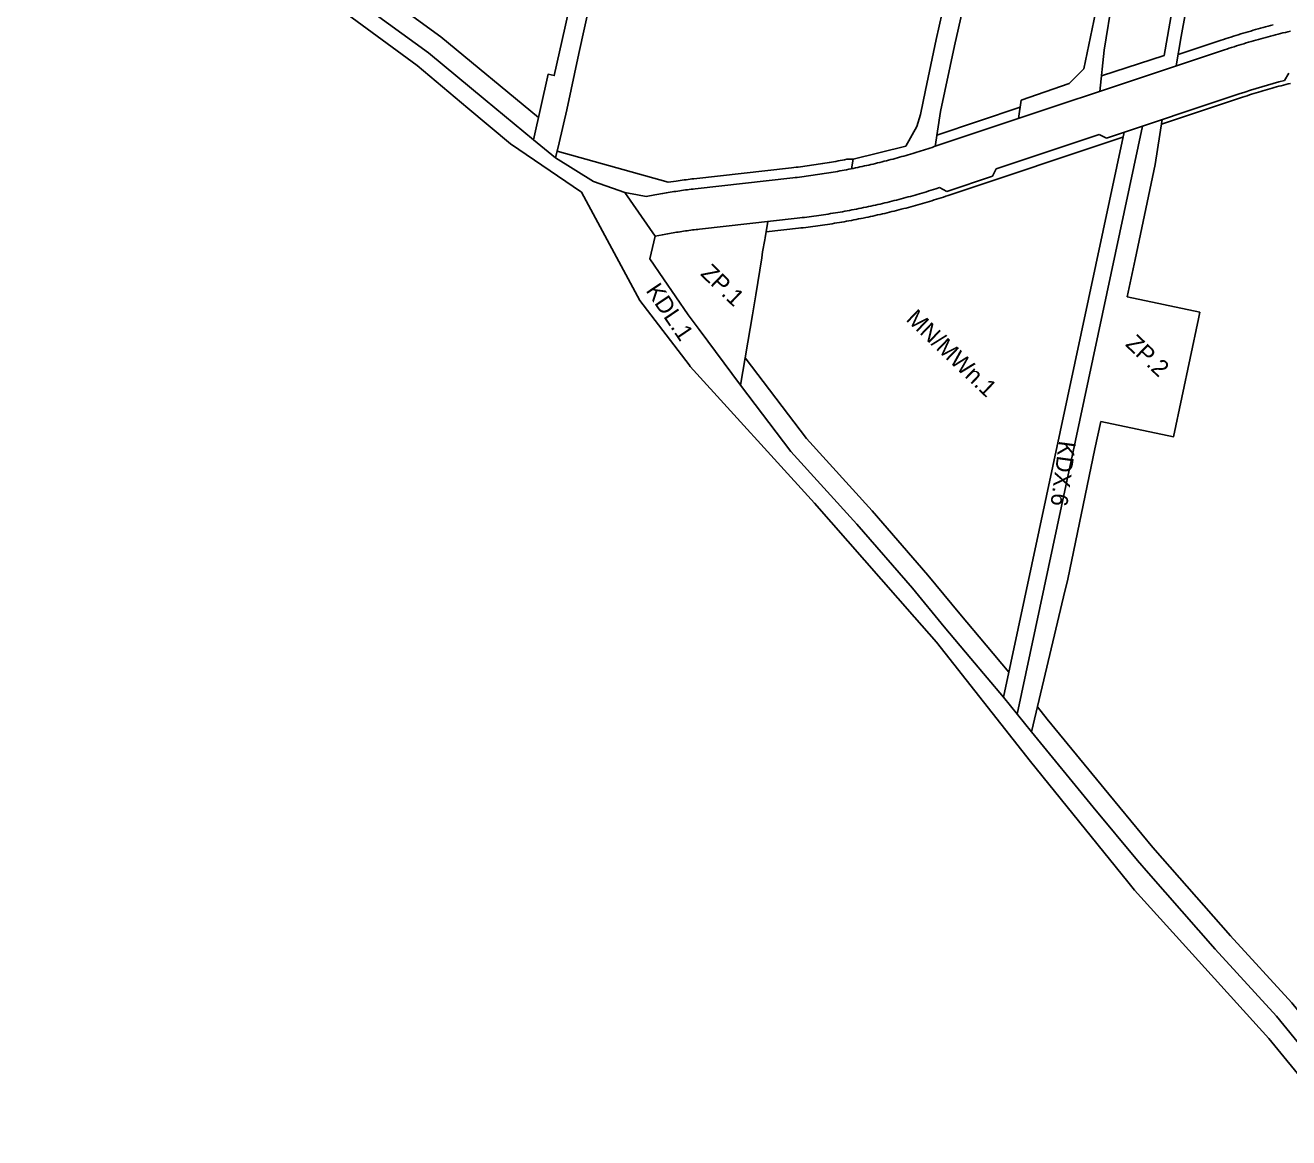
# Model space of a CAD drawing. Extents: x 7420063 to 7422255, y 5550978 to 5552824.
# Drawn here: x 7420947.8 to 7421321.6, y 5551350.9 to 5551680 of the extents above; entities that cross this region are included whole.
import ezdxf

# ---------------------------------------------------------------- set-up
doc = ezdxf.new("R2010")
doc.units = 0
for name, color, linetype in [('linie_rozgraniczajace', 7, 'Continuous'), ('linie_zabudowy_nieprzekraczalne', 7, 'Continuous'), ('oznaczenia_przeznaczen', 7, 'Continuous')]:
    doc.layers.add(name, color=color, linetype=linetype)

msp = doc.modelspace()

# ---------------------------------------------------------------- linework, layer by layer
at = {"layer": 'linie_rozgraniczajace'}
for p, q in [((7421320.41, 5551663.66), (7421321.64, 5551665.78)), ((7421306.95, 5551659.68), (7421267.73, 5551646.59)), ((7421241.3, 5551476.18), (7421278.41, 5551650.15)), ((7421265.52, 5551647.69), (7421267.73, 5551646.59)), ((7421233.99, 5551635.32), (7421235.1, 5551637.54)), ((7421220.51, 5551630.82), (7421218.28, 5551631.94)), ((7421233.99, 5551635.32), (7421220.51, 5551630.82)), ((7421134.22, 5551617.6), (7421125.18, 5551630.5)), ((7421295.35, 5551595.07), (7421273.84, 5551599.61))]:
    msp.add_line(p, q, dxfattribs=at)
for points in [[(7421098.19, 5551646.12), (7421102.49, 5551665.51), (7421104.31, 5551665.11), (7421107.41, 5551679.09), (7421110.27, 5551692), (7421113.2, 5551705.2), (7421116.05, 5551718.08), (7421118.99, 5551731.32), (7421121.85, 5551744.22), (7421124.78, 5551757.44), (7421127.64, 5551770.35), (7421130.57, 5551783.55), (7421133.44, 5551796.48), (7421136.37, 5551809.71), (7421139.22, 5551822.56), (7421142.14, 5551835.73), (7421147.18, 5551858.45), (7421142.87, 5551860.3), (7421144.36, 5551866.42)], [(7421154.11, 5551861.98), (7421150.54, 5551847.7), (7421144.27, 5551819.9), (7421143.15, 5551814.43), (7421141.13, 5551804.53), (7421134.5, 5551774.39), (7421133.74, 5551771.02), (7421126.58, 5551739.63), (7421111.64, 5551671.6), (7421108.05, 5551654.98), (7421105.74, 5551645.24), (7421104.68, 5551640.75)], [(7421192.24, 5551637.54), (7421192.8, 5551640.35), (7421208.3, 5551644.25), (7421211.64, 5551650.08), (7421212.65, 5551653.59), (7421214.19, 5551660.83), (7421217.37, 5551675.81), (7421220.84, 5551691.66), (7421224.12, 5551706.65), (7421227.62, 5551722.48), (7421230.93, 5551737.47), (7421234.37, 5551753.31), (7421237.62, 5551768.3), (7421241.08, 5551784.04), (7421244.4, 5551799.11), (7421248.11, 5551814.8), (7421251.22, 5551827.95)], [(7421256.32, 5551825.11), (7421251.4, 5551804.81), (7421243.81, 5551770.35), (7421239.56, 5551750.39), (7421236.22, 5551735.65), (7421232.72, 5551720.18), (7421226.82, 5551691.85), (7421222.72, 5551673.94), (7421218.61, 5551654.49), (7421217.04, 5551644.16)], [(7421241.69, 5551652.39), (7421242.49, 5551657.78), (7421256.68, 5551662.77), (7421261.06, 5551667.1), (7421264.93, 5551686), (7421270.26, 5551710.97), (7421275.92, 5551735.91), (7421281.27, 5551760.62), (7421286.7, 5551785.33), (7421291.46, 5551806.11)], [(7421295.18, 5551804.27), (7421289.3, 5551778.54), (7421287.92, 5551772.52), (7421285.32, 5551760.42), (7421281.44, 5551742.32), (7421280.86, 5551739.61), (7421277.39, 5551724.32), (7421276.81, 5551721.74), (7421273.3, 5551706.31), (7421272.66, 5551703.48), (7421269.89, 5551690.5), (7421269.46, 5551687.86), (7421266.99, 5551672.6), (7421265.78, 5551660.43)], [(7421266.23, 5551664.98), (7421284.76, 5551671.04), (7421287.2, 5551684.55), (7421290.87, 5551702.58), (7421294.72, 5551720.59), (7421298.61, 5551738.59), (7421302.65, 5551756.59), (7421306.63, 5551774.62), (7421310.59, 5551773.73), (7421303.16, 5551740.66), (7421301.45, 5551732.77), (7421298.14, 5551717.54), (7421292.21, 5551689.64), (7421289.79, 5551676.65), (7421288.34, 5551667.96)], [(7420943.09, 5551758.24), (7420950.48, 5551752.68), (7420965.32, 5551741.49), (7420966.91, 5551740.29), (7420981.78, 5551730.96), (7420990.3, 5551725.62), (7421000.22, 5551719.39), (7421009.04, 5551713.08), (7421019.38, 5551705.78), (7421029.95, 5551698.3), (7421047.42, 5551686.17), (7421067.1, 5551671.85), (7421083.92, 5551657.93), (7421098.19, 5551646.12), (7421104.68, 5551640.75)], [(7421339.77, 5551350.86), (7421315.74, 5551380.18), (7421275.97, 5551424.11), (7421274.02, 5551426.53), (7421245.28, 5551462.15), (7421217.47, 5551497.45), (7421210.95, 5551504.89), (7421181.34, 5551538.61), (7421144.57, 5551579.08), (7421144.2, 5551579.56), (7421129.6, 5551598.59), (7421112.4, 5551630.57), (7421091.37, 5551644.86), (7421078.71, 5551655.49), (7421063.74, 5551668.05), (7421026.78, 5551695.28)], [(7421131.49, 5551629.29), (7421134.09, 5551629.8), (7421134.66, 5551629.9), (7421135.22, 5551630.01), (7421135.78, 5551630.11), (7421136.35, 5551630.21), (7421136.91, 5551630.31), (7421137.48, 5551630.4), (7421138.04, 5551630.5), (7421138.61, 5551630.59), (7421139.17, 5551630.68), (7421139.74, 5551630.77), (7421140.31, 5551630.85), (7421140.87, 5551630.94), (7421141.44, 5551631.02), (7421142.01, 5551631.1), (7421142.58, 5551631.18), (7421143.14, 5551631.25), (7421143.71, 5551631.32), (7421144.28, 5551631.4), (7421144.85, 5551631.46), (7421145.42, 5551631.53), (7421145.98, 5551631.6), (7421174.89, 5551634.84), (7421175.56, 5551634.91), (7421176.23, 5551634.99), (7421176.89, 5551635.07), (7421177.56, 5551635.15), (7421178.22, 5551635.24), (7421178.89, 5551635.33), (7421179.55, 5551635.41), (7421180.22, 5551635.51), (7421180.88, 5551635.6), (7421181.55, 5551635.69), (7421182.21, 5551635.79), (7421182.87, 5551635.89), (7421183.54, 5551635.99), (7421184.2, 5551636.1), (7421184.86, 5551636.21), (7421185.52, 5551636.31), (7421186.19, 5551636.42), (7421186.85, 5551636.54), (7421187.51, 5551636.65), (7421188.17, 5551636.77), (7421188.83, 5551636.89), (7421189.49, 5551637.01), (7421190.15, 5551637.14), (7421190.81, 5551637.26), (7421191.47, 5551637.39), (7421192.13, 5551637.52), (7421192.79, 5551637.65), (7421193.44, 5551637.79), (7421194.1, 5551637.93), (7421194.76, 5551638.06), (7421195.42, 5551638.21), (7421196.07, 5551638.35), (7421196.73, 5551638.49), (7421197.38, 5551638.64), (7421198.04, 5551638.79), (7421198.69, 5551638.94), (7421199.35, 5551639.1), (7421200, 5551639.26), (7421200.65, 5551639.41), (7421201.3, 5551639.57), (7421201.95, 5551639.74), (7421202.61, 5551639.9), (7421203.26, 5551640.07), (7421203.91, 5551640.24), (7421204.56, 5551640.41), (7421205.2, 5551640.58), (7421205.85, 5551640.76), (7421206.5, 5551640.94), (7421207.15, 5551641.12), (7421207.79, 5551641.3), (7421208.44, 5551641.48), (7421209.08, 5551641.67), (7421209.73, 5551641.86), (7421210.37, 5551642.05), (7421211.01, 5551642.24), (7421211.65, 5551642.43), (7421212.29, 5551642.63), (7421212.93, 5551642.83), (7421213.57, 5551643.03), (7421214.21, 5551643.23), (7421214.85, 5551643.44), (7421215.49, 5551643.65), (7421216.12, 5551643.85), (7421216.77, 5551644.07), (7421302.6, 5551672.72), (7421303.31, 5551672.96), (7421304.02, 5551673.19), (7421304.73, 5551673.42), (7421305.45, 5551673.65), (7421306.17, 5551673.88), (7421306.88, 5551674.1), (7421307.6, 5551674.32), (7421308.32, 5551674.54), (7421309.04, 5551674.76), (7421309.76, 5551674.97), (7421310.48, 5551675.19), (7421311.21, 5551675.4), (7421311.93, 5551675.6), (7421312.65, 5551675.81), (7421313.38, 5551676.01), (7421314.1, 5551676.21), (7421314.83, 5551676.41), (7421315.56, 5551676.6), (7421316.28, 5551676.79), (7421317.01, 5551676.98), (7421317.74, 5551677.17), (7421318.47, 5551677.35), (7421319.2, 5551677.53), (7421319.93, 5551677.71), (7421320.67, 5551677.89), (7421321.4, 5551678.06), (7421322.13, 5551678.24)], [(7421284.18, 5551652.08), (7421282.12, 5551638.77), (7421276.2, 5551610.7), (7421273.84, 5551599.61)], [(7421235.1, 5551637.54), (7421265.52, 5551647.69)], [(7421237.26, 5551481.2), (7421272.9, 5551648.31)], [(7421125.18, 5551630.5), (7421115.9, 5551633.76), (7421104.68, 5551640.75)], [(7421134.22, 5551617.6), (7421136.34, 5551618.01), (7421136.86, 5551618.11), (7421137.38, 5551618.2), (7421137.9, 5551618.3), (7421138.43, 5551618.39), (7421138.95, 5551618.48), (7421139.47, 5551618.57), (7421139.99, 5551618.66), (7421140.51, 5551618.74), (7421141.03, 5551618.82), (7421141.56, 5551618.91), (7421142.08, 5551618.99), (7421142.6, 5551619.06), (7421143.13, 5551619.14), (7421143.65, 5551619.21), (7421144.18, 5551619.28), (7421144.7, 5551619.35), (7421145.22, 5551619.42), (7421145.75, 5551619.49), (7421146.27, 5551619.55), (7421146.8, 5551619.61), (7421147.33, 5551619.67), (7421176.24, 5551622.91), (7421176.94, 5551622.99), (7421177.64, 5551623.08), (7421178.35, 5551623.16), (7421179.05, 5551623.25), (7421179.76, 5551623.34), (7421180.46, 5551623.43), (7421181.16, 5551623.52), (7421181.87, 5551623.62), (7421182.57, 5551623.72), (7421183.27, 5551623.82), (7421183.98, 5551623.92), (7421184.68, 5551624.03), (7421185.38, 5551624.14), (7421186.08, 5551624.25), (7421186.78, 5551624.36), (7421187.49, 5551624.48), (7421188.19, 5551624.59), (7421188.89, 5551624.71), (7421189.59, 5551624.83), (7421190.29, 5551624.96), (7421190.99, 5551625.09), (7421191.69, 5551625.21), (7421192.39, 5551625.35), (7421193.08, 5551625.48), (7421193.78, 5551625.62), (7421194.48, 5551625.75), (7421195.18, 5551625.89), (7421195.87, 5551626.04), (7421196.57, 5551626.18), (7421197.27, 5551626.33), (7421197.96, 5551626.48), (7421198.66, 5551626.63), (7421199.35, 5551626.78), (7421200.04, 5551626.94), (7421200.74, 5551627.1), (7421201.43, 5551627.26), (7421202.12, 5551627.42), (7421202.81, 5551627.59), (7421203.5, 5551627.76), (7421204.19, 5551627.93), (7421204.88, 5551628.1), (7421205.57, 5551628.28), (7421206.26, 5551628.45), (7421206.95, 5551628.63), (7421207.64, 5551628.81), (7421208.32, 5551629), (7421209.01, 5551629.18), (7421209.69, 5551629.37), (7421210.38, 5551629.56), (7421211.06, 5551629.75), (7421211.75, 5551629.95), (7421212.43, 5551630.15), (7421213.11, 5551630.34), (7421213.79, 5551630.55), (7421214.47, 5551630.75), (7421215.15, 5551630.96), (7421215.83, 5551631.16), (7421216.51, 5551631.37), (7421217.19, 5551631.59), (7421218.28, 5551631.94)], [(7421125.18, 5551630.5), (7421129, 5551629.77), (7421131.49, 5551629.29)], [(7421159.44, 5551573.47), (7421162.99, 5551594.29), (7421163.98, 5551600.23), (7421165.72, 5551611.19), (7421165.91, 5551613), (7421166.59, 5551616.51), (7421166.69, 5551617.06), (7421167.5, 5551621.93)], [(7421134.21, 5551617.58), (7421132.6, 5551610.91), (7421136.69, 5551604.92), (7421143.94, 5551594.31), (7421147.17, 5551589.97)], [(7421295.35, 5551595.07), (7421294.94, 5551593.11), (7421287.59, 5551558.24), (7421266, 5551562.79)], [(7421147.17, 5551589.97), (7421159.44, 5551573.47), (7421174.34, 5551553.85), (7421193.88, 5551532.35), (7421210.31, 5551513.45), (7421219.71, 5551501.97), (7421227.54, 5551492.68), (7421237.26, 5551481.2), (7421245.54, 5551470.92), (7421263.74, 5551448.65), (7421276.92, 5551432.87), (7421280.18, 5551429.15), (7421299.92, 5551406.65)], [(7421266, 5551562.79), (7421264.28, 5551554.71), (7421256.27, 5551516.13), (7421255.04, 5551510.93), (7421245.54, 5551470.92)], [(7421299.92, 5551406.65), (7421318, 5551386.81), (7421326.34, 5551376.65)]]:
    msp.add_lwpolyline(points, dxfattribs=at)
msp.add_arc((7421370.99, 5551467.83), 202.25, 104.4833, 108.4608, dxfattribs=at)
at = {"layer": 'linie_zabudowy_nieprzekraczalne'}
for points in [[(7420947.8, 5551762.21), (7420970.32, 5551745.24), (7420993.49, 5551730.7), (7421003.56, 5551724.38), (7421012.52, 5551717.97), (7421022.85, 5551710.68), (7421033.39, 5551703.21), (7421050.89, 5551691.06), (7421070.78, 5551676.59), (7421099.65, 5551652.7)], [(7421288.9, 5551671.31), (7421301.65, 5551675.57), (7421302.37, 5551675.8), (7421303.09, 5551676.04), (7421303.81, 5551676.28), (7421304.54, 5551676.51), (7421305.27, 5551676.74), (7421305.99, 5551676.97), (7421306.72, 5551677.19), (7421307.45, 5551677.41), (7421308.18, 5551677.63), (7421308.91, 5551677.85), (7421309.64, 5551678.07), (7421310.38, 5551678.28), (7421311.11, 5551678.49), (7421311.84, 5551678.7), (7421312.58, 5551678.9), (7421313.31, 5551679.1), (7421314.05, 5551679.3), (7421314.79, 5551679.5), (7421315.53, 5551679.69), (7421316.26, 5551679.89), (7421317, 5551680.08)], [(7421322.12, 5551662.8), (7421321.44, 5551662.63), (7421320.76, 5551662.46), (7421320.08, 5551662.28), (7421319.41, 5551662.1), (7421318.73, 5551661.92), (7421318.05, 5551661.74), (7421317.38, 5551661.55), (7421316.7, 5551661.36), (7421316.03, 5551661.17), (7421315.36, 5551660.98), (7421314.68, 5551660.79), (7421314.01, 5551660.59), (7421313.34, 5551660.39), (7421312.67, 5551660.19), (7421312, 5551659.98), (7421311.34, 5551659.78), (7421310.67, 5551659.57), (7421310, 5551659.36), (7421309.34, 5551659.14), (7421308.67, 5551658.93), (7421308.01, 5551658.71), (7421307.34, 5551658.49), (7421283.96, 5551650.69)], [(7421217.55, 5551647.49), (7421242.18, 5551655.71)], [(7421272.6, 5551646.89), (7421221.5, 5551629.83), (7421220.83, 5551629.61), (7421220.14, 5551629.39), (7421219.46, 5551629.16), (7421218.78, 5551628.94), (7421218.09, 5551628.73), (7421217.4, 5551628.51), (7421216.72, 5551628.3), (7421216.03, 5551628.09), (7421215.34, 5551627.88), (7421214.65, 5551627.67), (7421213.96, 5551627.47), (7421213.27, 5551627.26), (7421212.57, 5551627.06), (7421211.88, 5551626.87), (7421211.19, 5551626.67), (7421210.49, 5551626.48), (7421209.8, 5551626.29), (7421209.1, 5551626.1), (7421208.41, 5551625.91), (7421207.71, 5551625.73), (7421207.01, 5551625.55), (7421206.31, 5551625.37), (7421205.62, 5551625.19), (7421204.92, 5551625.02), (7421204.22, 5551624.84), (7421203.52, 5551624.67), (7421202.81, 5551624.51), (7421202.11, 5551624.34), (7421201.41, 5551624.18), (7421200.71, 5551624.02), (7421200, 5551623.86), (7421199.3, 5551623.7), (7421198.6, 5551623.55), (7421197.89, 5551623.39), (7421197.19, 5551623.25), (7421196.48, 5551623.1), (7421195.77, 5551622.95), (7421195.07, 5551622.81), (7421194.36, 5551622.67), (7421193.65, 5551622.53), (7421192.94, 5551622.4), (7421192.24, 5551622.27), (7421191.53, 5551622.13), (7421190.82, 5551622.01), (7421190.11, 5551621.88), (7421189.4, 5551621.76), (7421188.69, 5551621.63), (7421187.98, 5551621.52), (7421187.27, 5551621.4), (7421186.55, 5551621.28), (7421185.84, 5551621.17), (7421185.13, 5551621.06), (7421184.42, 5551620.96), (7421183.71, 5551620.85), (7421182.99, 5551620.75), (7421182.28, 5551620.65), (7421181.57, 5551620.55), (7421180.85, 5551620.46), (7421180.14, 5551620.36), (7421179.43, 5551620.27), (7421178.71, 5551620.18), (7421178, 5551620.1), (7421177.28, 5551620.01), (7421176.58, 5551619.93), (7421166.99, 5551618.86)], [(7421105.14, 5551642.69), (7421138.01, 5551633.53)], [(7421137.98, 5551633.54), (7421140.44, 5551633.91), (7421141.02, 5551633.99), (7421141.6, 5551634.07), (7421142.18, 5551634.15), (7421142.75, 5551634.23), (7421143.33, 5551634.3), (7421143.91, 5551634.37), (7421144.49, 5551634.44), (7421145.07, 5551634.51), (7421145.64, 5551634.58), (7421174.56, 5551637.82), (7421175.22, 5551637.89), (7421175.87, 5551637.97), (7421176.53, 5551638.05), (7421177.19, 5551638.13), (7421177.84, 5551638.21), (7421178.5, 5551638.3), (7421179.15, 5551638.39), (7421179.81, 5551638.48), (7421180.46, 5551638.57), (7421181.11, 5551638.66), (7421181.77, 5551638.76), (7421182.42, 5551638.86), (7421183.07, 5551638.96), (7421183.73, 5551639.06), (7421184.38, 5551639.17), (7421185.03, 5551639.27), (7421185.69, 5551639.38), (7421186.34, 5551639.49), (7421186.99, 5551639.61), (7421187.64, 5551639.72), (7421188.29, 5551639.84), (7421188.94, 5551639.96), (7421189.59, 5551640.08), (7421190.24, 5551640.21), (7421190.89, 5551640.33), (7421192.8, 5551640.35)], [(7421160.82, 5551581.57), (7421178.96, 5551557.69), (7421198.37, 5551536.33), (7421214.89, 5551517.32), (7421224.32, 5551505.81), (7421232.12, 5551496.55), (7421238.84, 5551488.62)], [(7421247.29, 5551478.31), (7421250.2, 5551474.7), (7421268.37, 5551452.47), (7421281.47, 5551436.77), (7421304.43, 5551410.6)], [(7421304.35, 5551410.69), (7421322.54, 5551390.73), (7421330.98, 5551380.46), (7421347.61, 5551360.17)]]:
    msp.add_lwpolyline(points, dxfattribs=at)

# ---------------------------------------------------------------- texts
at = {"layer": 'oznaczenia_przeznaczen'}
for s, rotation, p in [('ZP.1', 316.2133, (7421147.34, 5551606.22)), ('KDL.1', 304.0507, (7421131.27, 5551601.51)), ('MN/MWn.1', 316.2133, (7421208.14, 5551592.77)), ('ZP.2', 316.2133, (7421273.07, 5551585.36)), ('KDX.6', 262.2713, (7421253.73, 5551557.23))]:
    msp.add_text(s, height=5, rotation=rotation, dxfattribs=at).set_placement(p)

doc.saveas('drawing.dxf')
